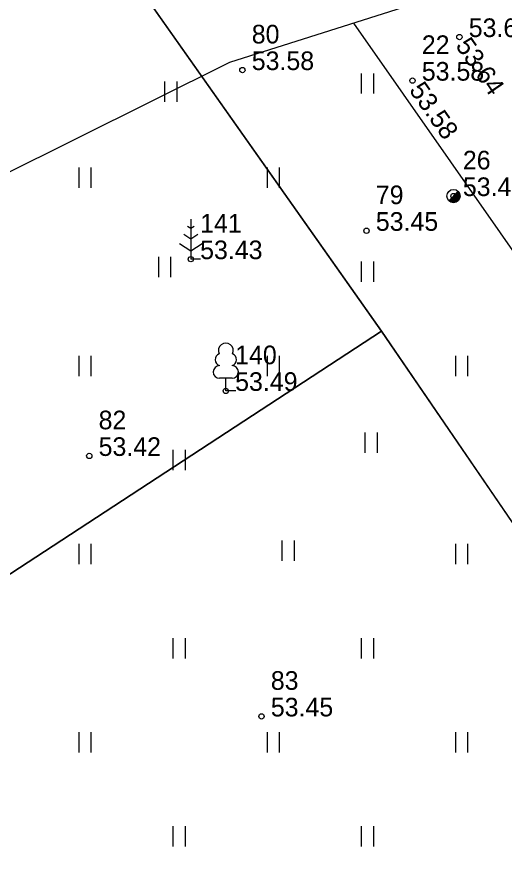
# Model space of a CAD drawing. Extents: x 538599 to 541973, y 6559689 to 6564516.
# Drawn here: x 540592.57 to 540610.89, y 6561313.83 to 6561345.76 of the extents above; entities that cross this region are included whole.
import ezdxf

# ---------------------------------------------------------------- set-up
doc = ezdxf.new("R2010")
doc.units = 0
for name, color, linetype in [('HALJASTUS', 7, 'Continuous'), ('KORGUS-EH2000', 7, 'Continuous'), ('MOOTKORG-EH2000', 7, 'Continuous'), ('MOOTMPUNKT', 7, 'Continuous'), ('MOOTNR', 7, 'Continuous'), ('MOOTPIIR', 7, 'Continuous'), ('PIIR', 7, 'Continuous'), ('POST', 7, 'Continuous'), ('PUU', 7, 'Continuous'), ('TEE', 7, 'Continuous')]:
    doc.layers.add(name, color=color, linetype=linetype)

msp = doc.modelspace()

# ---------------------------------------------------------------- linework, layer by layer
at = {"layer": 'HALJASTUS'}
for p, q in [((540605.496, 6561343.64), (540605.496, 6561342.879)), ((540605.951, 6561343.64), (540605.951, 6561342.879)), ((540598.115, 6561343.33), (540598.115, 6561342.568)), ((540598.57, 6561343.33), (540598.57, 6561342.568)), ((540594.89, 6561340.105), (540594.89, 6561339.343)), ((540595.345, 6561340.105), (540595.345, 6561339.343)), ((540601.961, 6561340.105), (540601.961, 6561339.343)), ((540602.416, 6561340.105), (540602.416, 6561339.343)), ((540597.88, 6561336.744), (540597.88, 6561335.982)), ((540598.335, 6561336.744), (540598.335, 6561335.982)), ((540605.496, 6561336.569), (540605.496, 6561335.808)), ((540605.951, 6561336.569), (540605.951, 6561335.808)), ((540594.89, 6561333.033), (540594.89, 6561332.272)), ((540595.345, 6561333.033), (540595.345, 6561332.272)), ((540601.961, 6561333.033), (540601.961, 6561332.272)), ((540602.416, 6561333.033), (540602.416, 6561332.272)), ((540609.032, 6561333.033), (540609.032, 6561332.272)), ((540609.487, 6561333.033), (540609.487, 6561332.272)), ((540605.634, 6561330.147), (540605.634, 6561329.386)), ((540606.089, 6561330.147), (540606.089, 6561329.386)), ((540598.425, 6561329.498), (540598.425, 6561328.737)), ((540598.88, 6561329.498), (540598.88, 6561328.737)), ((540594.89, 6561325.962), (540594.89, 6561325.201)), ((540595.345, 6561325.962), (540595.345, 6561325.201)), ((540602.518, 6561326.087), (540602.518, 6561325.326)), ((540602.973, 6561326.087), (540602.973, 6561325.326)), ((540609.032, 6561325.962), (540609.032, 6561325.201)), ((540609.487, 6561325.962), (540609.487, 6561325.201)), ((540598.425, 6561322.427), (540598.425, 6561321.666)), ((540598.88, 6561322.427), (540598.88, 6561321.666)), ((540605.496, 6561322.427), (540605.496, 6561321.666)), ((540605.951, 6561322.427), (540605.951, 6561321.666)), ((540594.89, 6561318.891), (540594.89, 6561318.13)), ((540595.345, 6561318.891), (540595.345, 6561318.13)), ((540601.961, 6561318.891), (540601.961, 6561318.13)), ((540602.416, 6561318.891), (540602.416, 6561318.13)), ((540609.032, 6561318.891), (540609.032, 6561318.13)), ((540609.487, 6561318.891), (540609.487, 6561318.13)), ((540598.425, 6561315.356), (540598.425, 6561314.595)), ((540598.88, 6561315.356), (540598.88, 6561314.595)), ((540605.496, 6561315.356), (540605.496, 6561314.595)), ((540605.951, 6561315.356), (540605.951, 6561314.595))]:
    msp.add_line(p, q, dxfattribs=at)
at = {"layer": 'KORGUS-EH2000'}
for centre in [(540609.183, 6561345.005), (540601.035, 6561343.764), (540607.421, 6561343.367), (540605.694, 6561337.727), (540595.285, 6561329.27), (540601.751, 6561319.484)]:
    msp.add_circle(centre, 0.1, dxfattribs=at)
at = {"layer": 'MOOTMPUNKT'}
for centre in [(540609.183, 6561345.005), (540601.035, 6561343.764), (540607.421, 6561343.367), (540608.962, 6561339.032), (540605.694, 6561337.727), (540599.097, 6561336.661), (540600.412, 6561331.713), (540595.285, 6561329.27), (540601.751, 6561319.484)]:
    msp.add_circle(centre, 0.1, dxfattribs=at)
at = {"layer": 'MOOTPIIR'}
msp.add_lwpolyline([(540611.814, 6561347.628), (540600.551, 6561344.045), (540588.991, 6561338.307), (540579.507, 6561329.749), (540567.369, 6561324.711), (540557.296, 6561315.504), (540537.549, 6561303.29), (540525.23, 6561316.048), (540500.22, 6561345.282), (540476.488, 6561371.995), (540449.028, 6561405.277), (540428.792, 6561428.292), (540413.022, 6561448.218), (540405.096, 6561459.889), (540393.809, 6561473.145)], dxfattribs=at)
at = {"layer": 'PIIR'}
msp.add_lwpolyline([(541045.65, 6560666.8), (540964.7, 6560765.19), (540868.94, 6560895.75), (540756.19, 6561084.56), (540744.95, 6561099.98), (540716.4, 6561150.76), (540687.02, 6561204.55), (540646.74, 6561272.89), (540640.63, 6561283.66), (540606.26, 6561333.96), (540569.6, 6561385.93), (540537.11, 6561431.06), (540500.82, 6561475.34), (540460.86, 6561522.64), (540423.13, 6561566.69), (540380.29, 6561616.49), (540342.1, 6561660.8)], dxfattribs=at)
for points in [[(540501.31, 6561330.86), (540569.6, 6561385.93), (540606.26, 6561333.96), (540535.92, 6561287.97)], [(540535.92, 6561287.97), (540606.26, 6561333.96), (540640.63, 6561283.66), (540573.77, 6561238.75)]]:
    msp.add_lwpolyline(points, close=True, dxfattribs=at)
at = {"layer": 'POST'}
msp.add_line((540608.785, 6561338.856), (540609.139, 6561339.209), dxfattribs=at)
msp.add_circle((540608.962, 6561339.032), 0.25, dxfattribs=at)
for radius, start, end in [(0.225, 224.8541, 45.0356), (0.2, 224.8427, 45.047), (0.175, 224.8281, 45.0616), (0.15, 224.8087, 45.081), (0.125, 224.7814, 45.1083), (0.1, 224.7406, 45.1491), (0.075, 224.6725, 45.2172), (0.05, 224.5363, 45.3534), (0.025, 224.1278, 45.7619)]:
    msp.add_arc((540608.962, 6561339.032), radius, start, end, dxfattribs=at)
at = {"layer": 'PUU'}
for p, q in [((540599.097, 6561338.161), (540599.097, 6561336.661)), ((540599.097, 6561337.811), (540598.973, 6561337.894)), ((540599.221, 6561337.894), (540599.097, 6561337.811)), ((540599.097, 6561337.411), (540598.83, 6561337.589)), ((540599.364, 6561337.589), (540599.097, 6561337.411)), ((540598.673, 6561337.25), (540599.097, 6561336.968)), ((540599.097, 6561336.968), (540599.521, 6561337.25)), ((540599.457, 6561336.661), (540599.097, 6561336.661)), ((540600.652, 6561332.188), (540600.172, 6561332.188)), ((540600.412, 6561331.713), (540600.412, 6561332.188)), ((540600.792, 6561331.713), (540600.412, 6561331.713))]:
    msp.add_line(p, q, dxfattribs=at)
for centre, radius, start, end in [((540600.412, 6561333.233), 0.277, 332.5799, 207.4201), ((540600.242, 6561332.886), 0.233, 109.0217, 253.1415), ((540600.582, 6561332.886), 0.233, 286.8508, 70.9859), ((540600.175, 6561332.425), 0.238, 90.0016, 269.3953), ((540600.649, 6561332.425), 0.238, 270.6047, 89.9984)]:
    msp.add_arc(centre, radius, start, end, dxfattribs=at)
at = {"layer": 'TEE'}
msp.add_lwpolyline([(540654.57, 6561271.748), (540648.314, 6561282.335), (540638.501, 6561297.54), (540627.363, 6561313.661), (540616.232, 6561329.779), (540605.221, 6561345.531)], dxfattribs=at)

# ---------------------------------------------------------------- texts
at = {"layer": 'KORGUS-EH2000'}
for s, rotation, p in [('53.64', 304.5279, (540609.014, 6561344.677)), ('53.58', 304.9535, (540607.271, 6561343.009))]:
    msp.add_text(s, height=0.7, rotation=rotation, dxfattribs=at).set_placement(p)
for s, p in [('53.58', (540601.385, 6561343.764)), ('53.45', (540606.044, 6561337.727)), ('53.42', (540595.635, 6561329.27)), ('53.45', (540602.101, 6561319.484))]:
    msp.add_text(s, height=0.7, dxfattribs=at).set_placement(p)
at = {"layer": 'MOOTKORG-EH2000'}
for s, p in [('53.64', (540609.533, 6561345.005)), ('53.58', (540601.385, 6561343.764)), ('53.58', (540607.771, 6561343.367)), ('53.47', (540609.312, 6561339.032)), ('53.45', (540606.044, 6561337.727)), ('53.43', (540599.447, 6561336.661)), ('53.49', (540600.762, 6561331.713)), ('53.42', (540595.635, 6561329.27)), ('53.45', (540602.101, 6561319.484))]:
    msp.add_text(s, height=0.7, dxfattribs=at).set_placement(p)
at = {"layer": 'MOOTNR'}
for s, p in [('80', (540601.385, 6561344.764)), ('22', (540607.771, 6561344.367)), ('26', (540609.312, 6561340.032)), ('79', (540606.044, 6561338.727)), ('141', (540599.447, 6561337.661)), ('140', (540600.762, 6561332.713)), ('82', (540595.635, 6561330.27)), ('83', (540602.101, 6561320.484))]:
    msp.add_text(s, height=0.7, dxfattribs=at).set_placement(p)

doc.saveas('drawing.dxf')
